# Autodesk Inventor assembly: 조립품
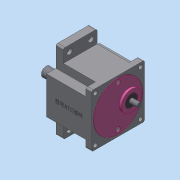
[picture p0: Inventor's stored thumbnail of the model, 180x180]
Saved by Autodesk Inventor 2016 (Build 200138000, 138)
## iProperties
Created: 2020-08
Part Number: 조립품
Material: 일반
Document SubType Name: Assembly
Designer: User
Author: User
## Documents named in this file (10)
- C:\Users\User\Desktop\700815V1005\조립품.iam
- C:\Users\User\Desktop\700815V1005\메인 축.ipt
- C:\Users\User\Desktop\700815V1005\베어링 608.ipt
- C:\Users\User\Desktop\700815V1005\베어링 6003.ipt
- C:\Users\User\Desktop\700815V1005\본체.ipt
- C:\Users\User\Desktop\700815V1005\볼트 M4.ipt
- C:\Users\User\Desktop\700815V1005\서브 축.ipt
- C:\Users\User\Desktop\700815V1005\오일 실 8 22 7.ipt
- C:\Users\User\Desktop\700815V1005\오일 실 17 32 8.ipt
- C:\Users\User\Desktop\700815V1005\커버.ipt
